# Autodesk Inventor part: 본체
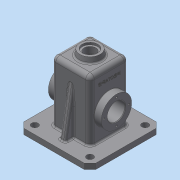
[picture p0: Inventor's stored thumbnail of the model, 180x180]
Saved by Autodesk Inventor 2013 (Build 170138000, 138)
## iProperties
Created: 2016-02
Part Number: 본체
Material: 일반
Document SubType Name: Modeling
Designer: Administrator
Density: 1 g/cm^3
Author: Administrator
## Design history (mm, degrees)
sketch "스케치1"
  geometry: L1 (10, 0)-(120, 0); L2 (130, 10)-(130, 120); L3 (120, 130)-(10, 130); L4 (0, 120)-(10, 130); L5 (0, 10)-(0, 120); L6 (130, 120)-(120, 130); L7 (130, 10)-(120, 0); L8 (0, 10)-(10, 0); C1 r 6 at (15, 15); C2 r 6 at (115, 15); C3 r 6 at (115, 115); C4 r 6 at (15, 115); 1 further point
  constraints: 16 end point, 5 perpendicular, 4 centre point, 1 horizontal
extrude "돌출1" new body sketch "스케치1" distance "d19" = 10; taper "d20" = 0 deg
sketch "스케치2"
  geometry: L1 (100, 65)-(100, 38); L2 (92, 30)-(38, 30); L3 (30, 38)-(30, 92); L4 (38, 100)-(92, 100); L5 (100, 92)-(100, 65); A1 r 8 centre (38, 92) between (38, 100) and (30, 92); A2 r 8 centre (92, 92) between (100, 92) and (92, 100); A3 r 8 centre (92, 38) between (92, 30) and (100, 38); A4 r 8 centre (38, 38) between (30, 38) and (38, 30); 1 further point
  constraints: 10 end point, 8 point on circle, 8 tangent, 4 centre point, 3 equal radius, 2 parallel, 1 perpendicular
extrude "돌출2" join sketch "스케치2" distance "d28" = 110; taper "d29" = 0 deg
sketch "스케치3"
  geometry: L1 (-30, 65)-(-30, 100) reference; L2 (-30, 100)-(-100, 100); L3 (-100, 100)-(-100, 30); L4 (-100, 30)-(-30, 30) reference; L5 (-30, 30)-(-30, 65) reference; L6 (-35, 95)-(-35, 65); L7 (-35, 65)-(-35, 35); L8 (-35, 35)-(-95, 35); L9 (-95, 35)-(-95, 95); L10 (-95, 95)-(-35, 95); 1 further point
  constraints: 20 end point, 4 perpendicular, 2 parallel, 2 vertical, 1 horizontal, 4 other
  dimensions: "d34" = 70 distance of L2.end L3.end; "d35" = 70 distance of L3.end L4.end; "d37" = 5 distance between parallel lines of L1 L6
extrude "돌출3" cut sketch "스케치3" distance "d38" = 115; taper "d39" = 0 deg
node "작업 평면1"
sketch "스케치4"
  geometry: L1 (30, 10)-(30, 120) reference; L2 (120, 10)-(10, 10) reference; L3 (0, 0)-(0, 10); L4 (15, 10)-(30, 95.069); L5 (30, 95.069)-(30, 10); L6 (15, 10)-(30, 10)
  constraints: 8 end point, 2 collinear, 2 point on line
  dimensions: "d42" = 10 distance of L3.start L3.end; "d43" = 15 distance of L3.end L4.start
extrude "돌출4" join sketch "스케치4" stored distance "d48" = 10; taper "d49" = 0 deg
node "작업 평면2"
sketch "스케치5"
  geometry: L1 (0, 0)-(-110, 0) reference; L2 (10, -38)-(10, 27); L3 (10, 27)-(-45, 27); L4 (0, -8)-(-110, -8) reference; C1 r 27.5 at (-45, 27)
  constraints: 4 end point, 2 perpendicular, 1 centre point, 1 coincident
  dimensions: "d51" = 65 distance of L2.start L2.end; "d52" = 55 distance of L2.end L3.end; "d53" = 55 diameter of C1
extrude "돌출5" join sketch "스케치5" distance "d54" = 13; taper "d55" = 0 deg
sketch "스케치6"
  geometry: L1 (0, 0)-(0, 60) reference; L2 (0, 60)-(115, 60) reference; L3 (0, 30)-(55, 30); C1 r 27.5 at (55, 30); 1 further point
  constraints: 2 end point, 1 centre point, 1 coincident, 1 midpoint, 1 parallel
  dimensions: "d56" = 55 distance of L3.start L3.end; "d57" = 55 diameter of C1
extrude "돌출6" join sketch "스케치6" distance "d58" = 7; taper "d59" = -45 deg
sketch "스케치7"
  geometry: C1 r 27.5 at (0, 0) reference; C2 r 16 at (0, 0); 1 further point
  constraints: 1 centre point, 1 coincident
  dimensions: "d60" = 32 diameter of C2
extrude "돌출7" cut sketch "스케치7" distance "d61" = 50; taper "d62" = 0 deg
sketch "스케치8"
  geometry: L1 (0, 0)-(-22.5, 0); C1 r 27.5 at (0, 0) reference; 1 further point
  constraints: 2 end point, 1 coincident, 1 horizontal, 1 horizontal alignment, 2 other
hole "구멍1" sketch "스케치8" at (-22.5, 0) diameter "d64" = 3.242; stored, may be unused: countersink angle "d68" = 90 deg, drill point angle "d70" = 118 deg; dims "d65" = 8, "d66" = 4, "d67" = 2, "d69" = 10
sketch "스케치9"
  geometry: C1 r 20 at (65, 65); 1 further point
  constraints: 1 centre point
  dimensions: "d75" = 40 diameter of C1
extrude "돌출8" join sketch "스케치9" distance "d76" = 10; taper "d77" = -10 deg
sketch "스케치10"
  geometry: C1 r 18.237 at (0, 0) reference; C2 r 14 at (0, 0); 1 further point
  constraints: 1 centre point, 1 coincident
  dimensions: "d78" = 28 diameter of C2
extrude "돌출9" cut sketch "스케치10" distance "d79" = 4; taper "d80" = 0 deg
sketch "스케치11"
  geometry: C1 r 14 at (0, 0) reference; C2 r 10.5 at (0, 0); 1 further point
  constraints: 1 centre point, 1 coincident
  dimensions: "d81" = 21 diameter of C2
extrude "돌출10" cut sketch "스케치11" distance "d82" = 40; taper "d83" = 0 deg
sketch "스케치12"
  geometry: L1 (-10, 8.763)-(-10, 45.237) reference; 2 further points
  constraints: 1 other
feature "엠보싱1" sketch "스케치12" dims "d85" = 0.5, "d86" = 0
chamfer "모따기1" distance "d87" = 1; stored, may be unused: second distance "d88" = 2, angle "d89" = 45 deg
fillet "모깎기1" dims "d90" = 3, "d91" = 8, "d92" = 0.5
node "솔리드1"
mirror "대칭1"
pattern_circular "원형 패턴1" dims angle "d72" = 360 deg
mirror "대칭2"
other parameters: "d40" = 65, "d50" = 65
